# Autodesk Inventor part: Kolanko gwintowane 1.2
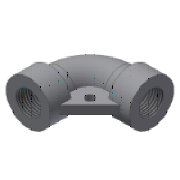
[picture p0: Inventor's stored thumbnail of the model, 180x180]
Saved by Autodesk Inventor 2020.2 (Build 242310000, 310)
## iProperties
Manager: www.cadconsulting.pl
Company: Fabian Stasiak CAD Consulting
Created: 2014-08
Part Number: Kolanko gwintowane 1.2
Material: Ogólny
Document SubType Name: Modeling
Designer: F.Stasiak
Standards Organization: ANSI
Language: pl-PL
Size Designation: 1/2
Categories: <MemberInstance><Categories><Category DisplayName="Rury cienko- i grubościenne" InternalName="4347fa0f-2144-441d-94cd-e3e15c92b736" Mnemonic="TUBEANDPIPE"><Cate
Density: 1 g/cm^3
Appearance: Domyślna
Catalog Web Link: www.expertbooks.pl
IsCustomPart: 0
Author: F.Stasiak
Subject: Zbiór ćwiczeń. Autodesk Inventor 2020. Kurs Professional
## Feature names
1. Przeciągnięcie1
2. Wyciągnięcie proste1 [Extrusion]
3. Wyciągnięcie proste2 [Extrusion]
4. Wyciągnięcie proste5 [Extrusion]
## Parameters: d0 = 45.7835 mm, d1 = 45.7835 mm, d2 = 22.89175 mm, d4 = 0, d5 = 0, d6 = 33.02 mm, d7 = 18.3134 mm, d9 = 15.748 mm, d10 = 0, d11 = 33.02 mm, d12 = 15.748 mm, d13 = 0, d19 = 19.8628 mm, d20 = 0, d21 = 19.8628 mm, d22 = 0, ID = 18.3134 mm, OD = 33.02 mm, GL = 15.748 mm, G = 3.175 mm, d23 = 3.175 mm, d24 = 6.35 mm, d26 = 6.35 mm, d27 = 0
